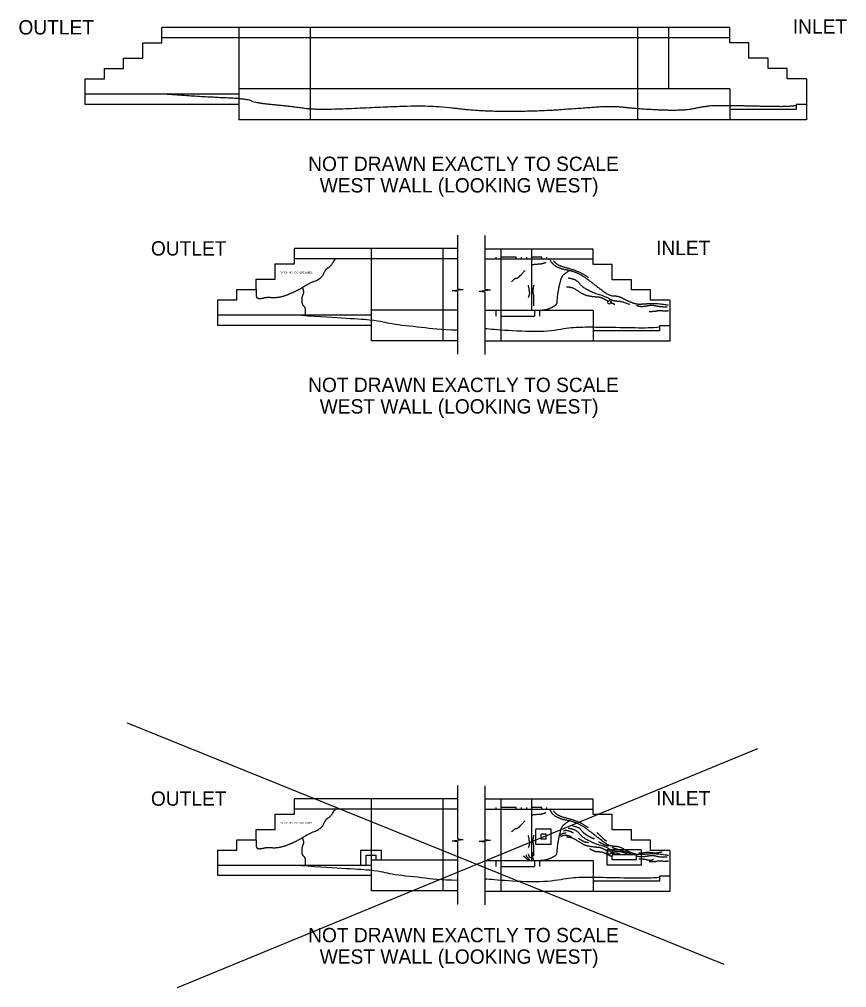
# Model space of a CAD drawing. Extents: x 21249 to 21441, y 6062 to 6293.
# Drawn here: x 21356.3 to 21437.2, y 6062.6 to 6157.2 of the extents above; entities that cross this region are included whole.
import ezdxf

# ---------------------------------------------------------------- set-up
doc = ezdxf.new("R2010")
doc.units = 0
for name, color, linetype in [('BR_P_Slab_Reinforcing', 7, 'Continuous'), ('DR_X_Culvert', 7, 'Continuous'), ('SC_Scratch1', 7, 'Continuous'), ('SC_Scratch2', 7, 'Continuous'), ('SH_Text', 7, 'Continuous'), ('XS_X_Ground_Line', 7, 'Continuous')]:
    doc.layers.add(name, color=color, linetype=linetype)

msp = doc.modelspace()

# ---------------------------------------------------------------- linework, layer by layer
at = {"layer": 'BR_P_Slab_Reinforcing'}
for p, q in [((21366.837, 6088.512), (21425.162, 6064.925)), ((21371.735, 6062.646), (21428.466, 6086.006))]:
    msp.add_line(p, q, dxfattribs=at)
at = {"layer": 'DR_X_Culvert'}
for p, q in [((21425.731, 6156.435), (21370.231, 6156.435)), ((21370.231, 6154.935), (21370.231, 6156.435)), ((21377.731, 6156.435), (21377.731, 6148.935)), ((21384.731, 6156.435), (21384.731, 6147.435)), ((21416.731, 6156.435), (21416.731, 6147.435)), ((21419.731, 6156.435), (21419.731, 6150.435)), ((21425.731, 6154.935), (21425.731, 6156.435)), ((21425.731, 6155.435), (21370.231, 6155.435)), ((21368.356, 6153.435), (21368.356, 6154.935)), ((21368.356, 6154.935), (21370.231, 6154.935)), ((21427.606, 6154.935), (21425.731, 6154.935)), ((21427.606, 6153.435), (21427.606, 6154.935)), ((21366.481, 6152.435), (21366.481, 6153.435)), ((21366.481, 6153.435), (21368.356, 6153.435)), ((21429.481, 6153.435), (21427.606, 6153.435)), ((21429.481, 6152.435), (21429.481, 6153.435)), ((21364.606, 6151.435), (21364.606, 6152.435)), ((21364.606, 6152.435), (21366.481, 6152.435)), ((21431.356, 6152.435), (21429.481, 6152.435)), ((21431.356, 6151.435), (21431.356, 6152.435)), ((21362.731, 6148.935), (21362.731, 6151.435)), ((21362.731, 6151.435), (21364.606, 6151.435)), ((21433.231, 6151.435), (21431.356, 6151.435)), ((21433.231, 6151.435), (21433.231, 6147.435)), ((21425.731, 6150.435), (21377.731, 6150.435)), ((21377.731, 6150.435), (21377.731, 6149.935)), ((21425.731, 6150.435), (21425.731, 6147.435)), ((21377.731, 6149.935), (21362.731, 6149.935)), ((21377.731, 6148.935), (21362.731, 6148.935)), ((21377.731, 6148.935), (21377.731, 6147.435)), ((21432.231, 6148.435), (21425.731, 6148.435)), ((21433.231, 6148.935), (21432.231, 6148.935)), ((21432.231, 6148.935), (21432.231, 6148.44)), ((21433.231, 6147.435), (21377.731, 6147.435)), ((21383.181, 6133.341), (21383.181, 6134.841)), ((21399.13, 6134.841), (21383.181, 6134.841)), ((21390.681, 6134.841), (21390.681, 6127.341)), ((21397.681, 6134.841), (21397.681, 6125.841)), ((21412.367, 6134.801), (21401.787, 6134.801)), ((21403.367, 6134.801), (21403.367, 6125.801)), ((21406.367, 6134.801), (21406.367, 6128.801)), ((21412.367, 6133.301), (21412.367, 6134.801)), ((21381.306, 6131.841), (21381.306, 6133.341)), ((21381.306, 6133.341), (21383.181, 6133.341)), ((21399.13, 6133.841), (21383.181, 6133.841)), ((21412.367, 6133.801), (21401.787, 6133.801)), ((21414.242, 6133.301), (21412.367, 6133.301)), ((21414.242, 6131.801), (21414.242, 6133.301)), ((21379.431, 6130.841), (21379.431, 6131.841)), ((21379.431, 6131.841), (21381.306, 6131.841)), ((21416.117, 6131.801), (21414.242, 6131.801)), ((21416.117, 6130.801), (21416.117, 6131.801)), ((21377.556, 6129.841), (21377.556, 6130.841)), ((21377.556, 6130.841), (21379.431, 6130.841)), ((21417.992, 6130.801), (21416.117, 6130.801)), ((21417.992, 6129.801), (21417.992, 6130.801)), ((21375.681, 6127.341), (21375.681, 6129.841)), ((21375.681, 6129.841), (21377.556, 6129.841)), ((21419.867, 6129.801), (21417.992, 6129.801)), ((21419.867, 6129.801), (21419.867, 6125.801)), ((21390.681, 6128.841), (21390.681, 6128.341)), ((21399.13, 6128.841), (21390.681, 6128.841)), ((21412.367, 6128.801), (21401.787, 6128.801)), ((21412.367, 6128.801), (21412.367, 6125.801)), ((21390.681, 6128.341), (21375.681, 6128.341)), ((21390.681, 6127.341), (21375.681, 6127.341)), ((21390.681, 6127.341), (21390.681, 6125.841)), ((21418.867, 6126.801), (21412.367, 6126.801)), ((21419.867, 6127.301), (21418.867, 6127.301)), ((21418.867, 6127.301), (21418.867, 6126.806)), ((21399.13, 6125.841), (21390.681, 6125.841)), ((21419.867, 6125.801), (21401.787, 6125.801)), ((21383.181, 6079.589), (21383.181, 6081.089)), ((21399.13, 6081.089), (21383.181, 6081.089)), ((21390.681, 6081.089), (21390.681, 6073.589)), ((21397.681, 6081.089), (21397.681, 6072.089)), ((21412.367, 6081.049), (21401.787, 6081.049)), ((21403.367, 6081.049), (21403.367, 6072.049)), ((21406.367, 6081.049), (21406.367, 6075.049)), ((21412.367, 6079.549), (21412.367, 6081.049)), ((21381.306, 6078.089), (21381.306, 6079.589)), ((21381.306, 6079.589), (21383.181, 6079.589)), ((21399.13, 6080.089), (21383.181, 6080.089)), ((21412.367, 6080.049), (21401.787, 6080.049)), ((21414.242, 6079.549), (21412.367, 6079.549)), ((21414.242, 6078.049), (21414.242, 6079.549)), ((21379.431, 6077.089), (21379.431, 6078.089)), ((21379.431, 6078.089), (21381.306, 6078.089)), ((21416.117, 6078.049), (21414.242, 6078.049)), ((21416.117, 6077.049), (21416.117, 6078.049)), ((21377.556, 6076.089), (21377.556, 6077.089)), ((21377.556, 6077.089), (21379.431, 6077.089)), ((21417.992, 6077.049), (21416.117, 6077.049)), ((21417.992, 6076.049), (21417.992, 6077.049)), ((21375.681, 6073.589), (21375.681, 6076.089)), ((21375.681, 6076.089), (21377.556, 6076.089)), ((21419.867, 6076.049), (21417.992, 6076.049)), ((21419.867, 6076.049), (21419.867, 6072.049)), ((21390.681, 6075.089), (21390.681, 6074.589)), ((21399.13, 6075.089), (21390.681, 6075.089)), ((21412.367, 6075.049), (21401.787, 6075.049)), ((21412.367, 6075.049), (21412.367, 6072.049)), ((21390.681, 6074.589), (21375.681, 6074.589)), ((21390.681, 6073.589), (21375.681, 6073.589)), ((21390.681, 6073.589), (21390.681, 6072.089)), ((21418.867, 6073.049), (21412.367, 6073.049)), ((21419.867, 6073.549), (21418.867, 6073.549)), ((21418.867, 6073.549), (21418.867, 6073.054)), ((21399.13, 6072.089), (21390.681, 6072.089)), ((21419.867, 6072.049), (21401.787, 6072.049))]:
    msp.add_line(p, q, dxfattribs=at)
for centre in [(21413.967, 6129.596), (21413.967, 6075.844)]:
    msp.add_circle(centre, 0.167, dxfattribs=at)
for points in [[(21406.367, 6133.277), (21407.008, 6133.348), (21407.324, 6133.348), (21407.768, 6133.503), (21407.768, 6133.503)], [(21419.741, 6129.298), (21418.524, 6129.5), (21417.34, 6129.409), (21416.617, 6129.373), (21415.744, 6129.715), (21414.906, 6130.191), (21413.995, 6130.191), (21412.939, 6130.982), (21412.084, 6131.659), (21411.149, 6132.32), (21410.235, 6132.672), (21409.316, 6132.823), (21408.396, 6133.264), (21408.144, 6133.801)], [(21411.913, 6132), (21411.359, 6132.413), (21410.18, 6132.857), (21409.253, 6133.079), (21408.668, 6133.411), (21408.527, 6133.663)], [(21405.702, 6132.688), (21405.331, 6132.285), (21404.985, 6131.922), (21404.711, 6131.922), (21404.413, 6131.608)], [(21410.068, 6132.682), (21409.491, 6132.348), (21409.209, 6131.914), (21408.846, 6130.261), (21408.846, 6129.394), (21408.403, 6129.092), (21407.617, 6128.801), (21407.194, 6128.801)], [(21415.955, 6129.373), (21415.13, 6129.686), (21414.536, 6129.686), (21414.104, 6129.828), (21413.692, 6130.112), (21412.441, 6130.493), (21411.344, 6131.047), (21410.824, 6131.726), (21410.13, 6131.944), (21409.929, 6131.944)], [(21383.948, 6131.05), (21384.14, 6130.595), (21383.888, 6130.129), (21383.888, 6129.396), (21384.316, 6129.02), (21384.203, 6128.341)], [(21406.02, 6131.263), (21406.149, 6130.656), (21406.149, 6130.334), (21406.033, 6130.076)], [(21406.587, 6129.256), (21406.587, 6129.756), (21406.587, 6130.256), (21406.484, 6130.772), (21406.587, 6131.282)], [(21413.838, 6129.702), (21413.516, 6129.882), (21413, 6130.101), (21412.67, 6130.101), (21411.725, 6130.22), (21411.081, 6130.576), (21410.287, 6131.088), (21409.787, 6131.088)], [(21414.485, 6129.373), (21414.294, 6129.48), (21414.227, 6129.48), (21414.126, 6129.549)], [(21419.621, 6129.127), (21418.926, 6129.127), (21418.173, 6129.318), (21417.638, 6129.222), (21416.968, 6129.131), (21416.617, 6129.267)], [(21417.858, 6128.708), (21418.436, 6128.708), (21418.844, 6128.827), (21419.54, 6128.719), (21419.736, 6128.791)], [(21406.367, 6079.525), (21407.008, 6079.596), (21407.324, 6079.596), (21407.768, 6079.751), (21407.768, 6079.751)], [(21419.741, 6075.546), (21418.524, 6075.748), (21417.34, 6075.657), (21416.617, 6075.621), (21415.744, 6075.963), (21414.906, 6076.439), (21413.995, 6076.439), (21412.939, 6077.229), (21412.084, 6077.907), (21411.149, 6078.568), (21410.235, 6078.92), (21409.316, 6079.071), (21408.396, 6079.512), (21408.144, 6080.049)], [(21411.913, 6078.248), (21411.359, 6078.661), (21410.18, 6079.105), (21409.253, 6079.326), (21408.668, 6079.659), (21408.527, 6079.911)], [(21405.702, 6078.936), (21405.331, 6078.533), (21404.985, 6078.17), (21404.711, 6078.17), (21404.413, 6077.856)], [(21410.068, 6078.929), (21409.491, 6078.596), (21409.209, 6078.162), (21408.846, 6076.509), (21408.846, 6075.642), (21408.403, 6075.339), (21407.617, 6075.049), (21407.194, 6075.049)], [(21410.327, 6078.473), (21411.037, 6078.295), (21411.295, 6077.892), (21411.746, 6077.553), (21412.23, 6077.279), (21412.528, 6077.191)], [(21406.02, 6077.511), (21406.149, 6076.904), (21406.149, 6076.581), (21406.033, 6076.323)], [(21406.587, 6075.504), (21406.587, 6076.004), (21406.587, 6076.504), (21406.484, 6077.02), (21406.587, 6077.53)], [(21409.065, 6077.454), (21409.249, 6077.67), (21409.6, 6077.765), (21409.752, 6077.765)], [(21409.184, 6077.398), (21409.44, 6077.538), (21409.861, 6077.538), (21410.113, 6077.455), (21410.233, 6077.385)], [(21410.439, 6077.749), (21410.187, 6077.897), (21409.667, 6078.025), (21409.469, 6077.926)], [(21415.955, 6075.621), (21415.13, 6075.934), (21414.536, 6075.934), (21414.104, 6076.076), (21413.692, 6076.36), (21412.441, 6076.74), (21411.344, 6077.295), (21410.824, 6077.974), (21410.13, 6078.192), (21409.929, 6078.192)], [(21412.742, 6077.807), (21413.109, 6077.487), (21413.428, 6077.126), (21413.671, 6076.992)], [(21383.948, 6077.298), (21384.14, 6076.843), (21383.888, 6076.377), (21383.888, 6075.644), (21384.316, 6075.268), (21384.203, 6074.589)], [(21413.838, 6075.95), (21413.516, 6076.13), (21413, 6076.349), (21412.67, 6076.349), (21411.725, 6076.468), (21411.081, 6076.823), (21410.287, 6077.335), (21409.787, 6077.335)], [(21410.952, 6077.245), (21411.293, 6076.992), (21411.721, 6076.837), (21411.922, 6076.837)], [(21412.897, 6076.904), (21413.248, 6076.724), (21413.604, 6076.548), (21413.882, 6076.481)], [(21406.226, 6075.049), (21406.091, 6075.259), (21405.845, 6075.452), (21405.845, 6075.633)], [(21406.013, 6075.691), (21406.136, 6075.388), (21406.252, 6075.388), (21406.367, 6075.323)], [(21406.613, 6075.049), (21406.465, 6075.31), (21406.465, 6075.542), (21406.465, 6075.856)], [(21414.242, 6075.42), (21413.821, 6075.622), (21413.321, 6075.896), (21412.693, 6075.896), (21412.298, 6076.033), (21412.056, 6076.195)], [(21414.485, 6075.621), (21414.294, 6075.728), (21414.227, 6075.728), (21414.126, 6075.797)], [(21415.096, 6075.621), (21414.783, 6075.778), (21414.502, 6075.778), (21414.304, 6075.844), (21414.217, 6075.91)], [(21416.182, 6075.621), (21415.872, 6075.798), (21415.48, 6075.922), (21414.927, 6076.096), (21414.424, 6076.248), (21414.259, 6076.327)], [(21416.858, 6075.813), (21417.193, 6075.813), (21417.693, 6075.906), (21417.993, 6075.854), (21418.581, 6075.787), (21419.112, 6075.916)], [(21405.555, 6075.53), (21405.794, 6075.31), (21405.968, 6075.181), (21405.962, 6075.049), (21405.955, 6075.049)], [(21419.621, 6075.375), (21418.926, 6075.375), (21418.173, 6075.566), (21417.638, 6075.469), (21416.968, 6075.379), (21416.617, 6075.515)], [(21416.842, 6075.224), (21417.342, 6075.224), (21417.828, 6075.106), (21418.194, 6075.106), (21418.281, 6075.199)], [(21417.858, 6074.956), (21418.436, 6074.956), (21418.844, 6075.075), (21419.54, 6074.966), (21419.736, 6075.039)]]:
    msp.add_open_spline(points, degree=2, dxfattribs=at)
at = {"layer": 'SC_Scratch1'}
for p, q in [((21404.867, 6133.999), (21403.367, 6133.999)), ((21403.367, 6133.999), (21403.367, 6133.801)), ((21404.867, 6133.801), (21404.867, 6133.999)), ((21407.367, 6133.999), (21406.367, 6133.999)), ((21406.367, 6133.999), (21406.367, 6133.801)), ((21407.367, 6133.801), (21407.367, 6133.999)), ((21403.367, 6128.801), (21403.367, 6128.239)), ((21406.645, 6128.801), (21406.645, 6128.239)), ((21403.367, 6128.239), (21406.645, 6128.239)), ((21404.867, 6080.246), (21403.367, 6080.246)), ((21403.367, 6080.246), (21403.367, 6080.049)), ((21404.867, 6080.049), (21404.867, 6080.246)), ((21407.367, 6080.246), (21406.367, 6080.246)), ((21406.367, 6080.246), (21406.367, 6080.049)), ((21407.367, 6080.049), (21407.367, 6080.246)), ((21407.29, 6077.14), (21407.29, 6077.64)), ((21407.79, 6077.64), (21407.29, 6077.64)), ((21407.79, 6077.14), (21407.79, 6077.64)), ((21407.79, 6077.14), (21407.29, 6077.14)), ((21390.181, 6075.589), (21391.181, 6075.589)), ((21390.181, 6074.589), (21390.181, 6075.589)), ((21391.181, 6075.089), (21391.181, 6075.589)), ((21416.617, 6075.621), (21414.242, 6075.621)), ((21414.242, 6075.121), (21414.242, 6075.621)), ((21416.617, 6075.121), (21416.617, 6075.621)), ((21403.367, 6075.049), (21403.367, 6074.487)), ((21406.645, 6075.049), (21406.645, 6074.487)), ((21416.617, 6075.121), (21414.242, 6075.121)), ((21403.367, 6074.487), (21406.645, 6074.487))]:
    msp.add_line(p, q, dxfattribs=at)
for points in [[(21379.431, 6130.841), (21379.431, 6130.385), (21379.431, 6130.169), (21379.561, 6129.972), (21379.974, 6129.972), (21380.464, 6130.112), (21381.31, 6130.045), (21382.111, 6130.185), (21382.988, 6130.537), (21383.814, 6130.951), (21384.499, 6131.404), (21385.855, 6131.938), (21386.248, 6132.867), (21386.752, 6133.119), (21387.181, 6133.841)], [(21379.431, 6077.089), (21379.431, 6076.633), (21379.431, 6076.416), (21379.561, 6076.22), (21379.974, 6076.22), (21380.464, 6076.36), (21381.31, 6076.293), (21382.111, 6076.432), (21382.988, 6076.785), (21383.814, 6077.199), (21384.499, 6077.652), (21385.855, 6078.186), (21386.248, 6079.115), (21386.752, 6079.367), (21387.181, 6080.089)]]:
    msp.add_open_spline(points, degree=2, dxfattribs=at)
at = {"layer": 'SC_Scratch2'}
for p, q in [((21402.867, 6133.999), (21402.867, 6133.801)), ((21405.367, 6133.801), (21405.367, 6133.999)), ((21405.867, 6133.999), (21405.867, 6133.801)), ((21407.867, 6133.801), (21407.867, 6133.999)), ((21402.867, 6128.801), (21402.867, 6128.239)), ((21407.145, 6128.801), (21407.145, 6128.239)), ((21402.867, 6080.246), (21402.867, 6080.049)), ((21405.367, 6080.049), (21405.367, 6080.246)), ((21405.867, 6080.246), (21405.867, 6080.049)), ((21407.867, 6080.049), (21407.867, 6080.246)), ((21408.29, 6078.14), (21406.79, 6078.14)), ((21406.79, 6076.64), (21406.79, 6078.14)), ((21408.29, 6076.64), (21408.29, 6078.14)), ((21408.29, 6076.64), (21406.79, 6076.64)), ((21389.681, 6076.089), (21391.681, 6076.089)), ((21389.681, 6074.589), (21389.681, 6076.089)), ((21391.681, 6075.089), (21391.681, 6076.089)), ((21417.117, 6076.121), (21413.742, 6076.121)), ((21413.742, 6074.621), (21413.742, 6076.121)), ((21417.117, 6074.621), (21417.117, 6076.121)), ((21402.867, 6075.049), (21402.867, 6074.487)), ((21407.145, 6075.049), (21407.145, 6074.487)), ((21417.117, 6074.621), (21413.742, 6074.621))]:
    msp.add_line(p, q, dxfattribs=at)
at = {"layer": 'SH_Text'}
for p, q in [((21399.13, 6136.148), (21399.13, 6130.918)), ((21401.787, 6136.108), (21401.787, 6130.878)), ((21398.582, 6130.733), (21399.678, 6130.856)), ((21398.582, 6130.733), (21399.13, 6130.671)), ((21399.13, 6130.918), (21399.678, 6130.856)), ((21399.13, 6130.671), (21399.13, 6124.535)), ((21401.239, 6130.692), (21402.335, 6130.816)), ((21401.239, 6130.692), (21401.787, 6130.63)), ((21401.787, 6130.878), (21402.335, 6130.816)), ((21401.787, 6130.63), (21401.787, 6124.494)), ((21399.13, 6082.396), (21399.13, 6077.166)), ((21401.787, 6082.356), (21401.787, 6077.126)), ((21398.582, 6076.98), (21399.678, 6077.104)), ((21398.582, 6076.98), (21399.13, 6076.918)), ((21399.13, 6077.166), (21399.678, 6077.104)), ((21399.13, 6076.918), (21399.13, 6070.782)), ((21401.239, 6076.94), (21402.335, 6077.064)), ((21401.239, 6076.94), (21401.787, 6076.878)), ((21401.787, 6077.126), (21402.335, 6077.064)), ((21401.787, 6076.878), (21401.787, 6070.742))]:
    msp.add_line(p, q, dxfattribs=at)
at = {"layer": 'XS_X_Ground_Line'}
for points, degree in [([(21432.231, 6148.806), (21431.525, 6148.708), (21430.025, 6148.708), (21426.698, 6148.787), (21425.198, 6148.787), (21423.462, 6148.787), (21421.194, 6148.269), (21416.531, 6148.487), (21414.238, 6148.769), (21411.202, 6148.539), (21406.798, 6148.233), (21401.394, 6148.233), (21397.07, 6148.753), (21393.708, 6148.753), (21385.441, 6148.333), (21382.839, 6148.733), (21379.336, 6149.054), (21378.596, 6149.474), (21373.992, 6149.667), (21370.231, 6149.935)], 2), ([(21399.13, 6126.876), (21397.457, 6126.882), (21395.744, 6127.143), (21392.286, 6127.46), (21391.545, 6127.88), (21386.942, 6128.073), (21383.181, 6128.341)], 3), ([(21418.867, 6127.172), (21418.161, 6127.074), (21416.661, 6127.074), (21413.333, 6127.152), (21411.833, 6127.152), (21410.097, 6127.152), (21407.829, 6126.635), (21403.787, 6126.824), (21402.311, 6126.967), (21401.787, 6127.004)], 3), ([(21399.13, 6073.124), (21397.457, 6073.13), (21395.744, 6073.391), (21392.286, 6073.707), (21391.545, 6074.128), (21386.942, 6074.321), (21383.181, 6074.589)], 3), ([(21418.867, 6073.42), (21418.161, 6073.321), (21416.661, 6073.321), (21413.333, 6073.4), (21411.833, 6073.4), (21410.097, 6073.4), (21407.829, 6072.883), (21403.787, 6073.072), (21402.311, 6073.215), (21401.787, 6073.252)], 3)]:
    msp.add_open_spline(points, degree=degree, dxfattribs=at)

# ---------------------------------------------------------------- texts
at = {"layer": 'SC_Scratch1'}
for s, height, p in [('OUTLET', 1.4, (21356.199, 6155.76)), ('INLET', 1.4, (21431.898, 6155.837)), ('NOT DRAWN EXACTLY TO SCALE', 1.4, (21384.522, 6142.425)), ('WEST WALL (LOOKING WEST)', 1.4, (21385.651, 6140.325)), ('OUTLET', 1.4, (21369.149, 6134.166)), ('INLET', 1.4, (21418.534, 6134.202)), ('PATCHING - DO NOT LABEL', 0.175, (21381.734, 6132.408)), ('NOT DRAWN EXACTLY TO SCALE', 1.4, (21384.522, 6120.831)), ('WEST WALL (LOOKING WEST)', 1.4, (21385.651, 6118.731)), ('OUTLET', 1.4, (21369.149, 6080.414)), ('INLET', 1.4, (21418.534, 6080.45)), ('PATCHING - DO NOT LABEL', 0.175, (21381.734, 6078.656)), ('NOT DRAWN EXACTLY TO SCALE', 1.4, (21384.522, 6067.079)), ('WEST WALL (LOOKING WEST)', 1.4, (21385.651, 6064.979))]:
    msp.add_text(s, height=height, dxfattribs=at).set_placement(p)

doc.saveas('drawing.dxf')
